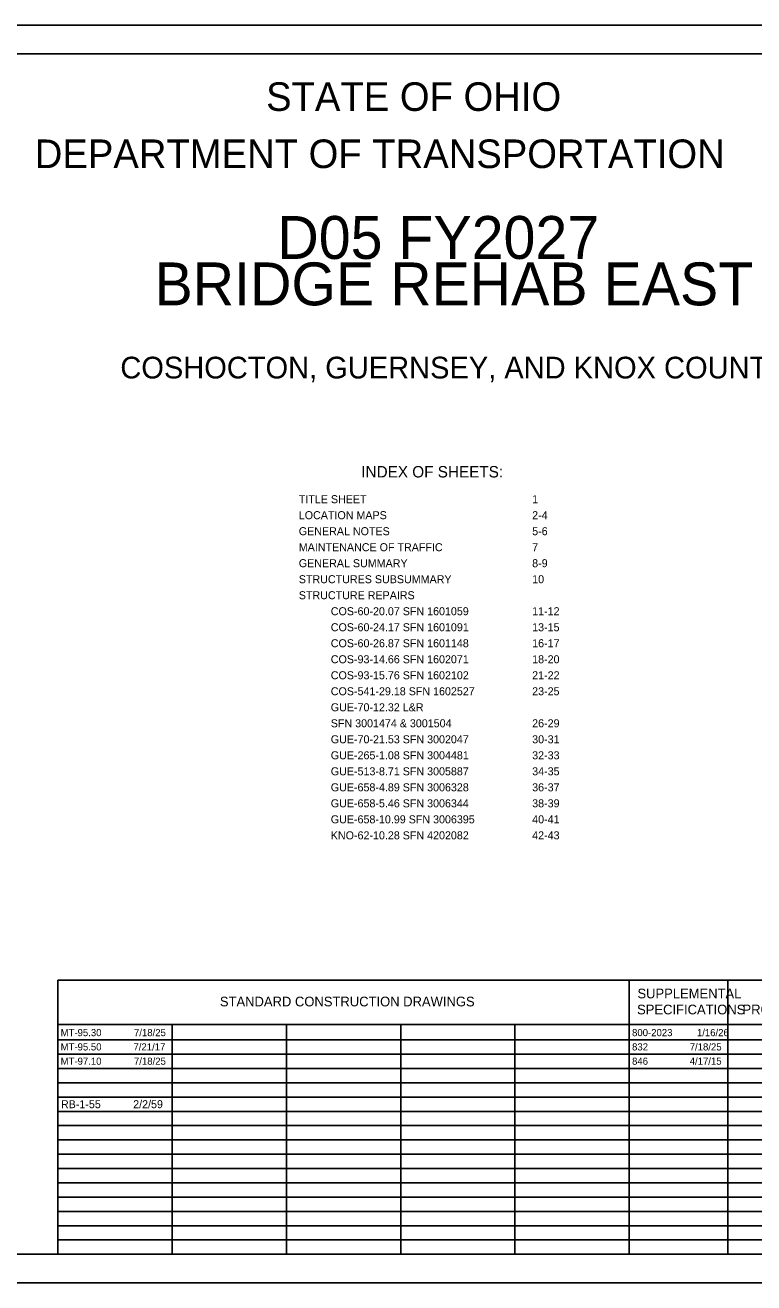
# Model space of a CAD drawing. Extents: x 0 to 34, y 0 to 22.
# Drawn here: x 9.58 to 22.33, y 0 to 22 of the extents above; entities that cross this region are included whole.
import ezdxf

# ---------------------------------------------------------------- set-up
doc = ezdxf.new("R2010")
doc.units = 0
for name, color, linetype in [('Default', 7, 'Continuous'), ('SH_Border', 7, 'Continuous'), ('SH_Cut_Line', 7, 'Continuous'), ('SH_Data', 7, 'Continuous'), ('SH_Text', 7, 'Continuous')]:
    doc.layers.add(name, color=color, linetype=linetype)

msp = doc.modelspace()

# ---------------------------------------------------------------- linework, layer by layer
at = {"layer": 'SH_Border'}
msp.add_lwpolyline([(1.5, 21.5), (33.5, 21.5), (33.5, 0.5), (1.5, 0.5)], close=True, dxfattribs=at)
at = {"layer": 'SH_Cut_Line'}
msp.add_lwpolyline([(0, 0), (34, 0), (34, 22), (0, 22)], close=True, dxfattribs=at)
at = {"layer": 'SH_Data'}
for p, q in [((10.15, 5.292), (23.6, 5.292)), ((10.15, 0.5), (10.15, 5.292)), ((20.15, 0.5), (20.15, 5.292)), ((21.875, 0.5), (21.875, 5.292)), ((10.15, 4.521), (23.6, 4.521)), ((12.15, 0.5), (12.15, 4.521)), ((14.15, 0.5), (14.15, 4.521)), ((16.15, 0.5), (16.15, 4.521)), ((18.15, 0.5), (18.15, 4.521)), ((10.15, 4.25), (23.6, 4.25)), ((10.15, 4), (23.6, 4)), ((10.15, 3.75), (23.6, 3.75)), ((10.15, 3.5), (23.6, 3.5)), ((10.15, 3.25), (23.6, 3.25)), ((10.15, 3), (23.6, 3)), ((10.15, 2.75), (23.6, 2.75)), ((10.15, 2.5), (23.6, 2.5)), ((10.15, 2.25), (23.6, 2.25)), ((10.15, 2), (23.6, 2)), ((10.15, 1.75), (23.6, 1.75)), ((10.15, 1.5), (23.6, 1.5)), ((10.15, 1.25), (23.6, 1.25)), ((10.15, 1), (23.6, 1)), ((10.15, 0.75), (23.6, 0.75))]:
    msp.add_line(p, q, dxfattribs=at)

# ---------------------------------------------------------------- texts
at = {"layer": 'Default'}
for s, p in [('MT-95.30', (10.199, 4.315)), ('7/18/25', (11.483, 4.315)), ('800-2023', (20.199, 4.315)), ('1/16/26', (21.334, 4.315)), ('MT-95.50', (10.199, 4.065)), ('7/21/17', (11.474, 4.065)), ('832', (20.199, 4.065)), ('7/18/25', (21.208, 4.065)), ('MT-97.10', (10.199, 3.815)), ('7/18/25', (11.483, 3.815)), ('846', (20.199, 3.815)), ('4/17/15', (21.208, 3.815))]:
    msp.add_text(s, height=0.125, dxfattribs=at).set_placement(p)
at = {"layer": 'SH_Text'}
for s, height, p in [('STATE OF OHIO', 0.5, (13.795, 20.5)), ('DEPARTMENT OF TRANSPORTATION', 0.5, (9.747, 19.5)), ('D05 FY2027', 0.75, (13.992, 17.911)), ('BRIDGE REHAB EAST', 0.75, (11.842, 17.099)), ('COSHOCTON, GUERNSEY, AND KNOX COUNTIES', 0.38, (11.244, 15.82)), ('INDEX OF SHEETS:', 0.2, (15.461, 14.088)), ('TITLE SHEET', 0.14, (14.367, 13.638)), ('1', 0.14, (18.451, 13.638)), ('LOCATION MAPS', 0.14, (14.367, 13.358)), ('2-4', 0.14, (18.451, 13.358)), ('GENERAL NOTES', 0.14, (14.367, 13.078)), ('5-6', 0.14, (18.451, 13.078)), ('MAINTENANCE OF TRAFFIC', 0.14, (14.367, 12.798)), ('7', 0.14, (18.451, 12.798)), ('GENERAL SUMMARY', 0.14, (14.367, 12.518)), ('8-9', 0.14, (18.451, 12.518)), ('STRUCTURES SUBSUMMARY', 0.14, (14.367, 12.238)), ('10', 0.14, (18.451, 12.238)), ('STRUCTURE REPAIRS', 0.14, (14.367, 11.958)), ('COS-60-20.07 SFN 1601059', 0.14, (14.927, 11.678)), ('11-12', 0.14, (18.451, 11.678)), ('COS-60-24.17 SFN 1601091', 0.14, (14.927, 11.398)), ('13-15', 0.14, (18.451, 11.398)), ('COS-60-26.87 SFN 1601148', 0.14, (14.927, 11.118)), ('16-17', 0.14, (18.451, 11.118)), ('COS-93-14.66 SFN 1602071', 0.14, (14.927, 10.838)), ('18-20', 0.14, (18.451, 10.838)), ('COS-93-15.76 SFN 1602102', 0.14, (14.927, 10.558)), ('21-22', 0.14, (18.451, 10.558)), ('COS-541-29.18 SFN 1602527', 0.14, (14.927, 10.278)), ('23-25', 0.14, (18.451, 10.278)), ('GUE-70-12.32 L&R ', 0.14, (14.927, 9.998)), ('SFN 3001474 & 3001504', 0.14, (14.927, 9.718)), ('26-29', 0.14, (18.451, 9.718)), ('GUE-70-21.53 SFN 3002047', 0.14, (14.927, 9.438)), ('30-31', 0.14, (18.451, 9.438)), ('GUE-265-1.08 SFN 3004481', 0.14, (14.927, 9.158)), ('32-33', 0.14, (18.451, 9.158)), ('GUE-513-8.71 SFN 3005887', 0.14, (14.927, 8.878)), ('34-35', 0.14, (18.451, 8.878)), ('GUE-658-4.89 SFN 3006328', 0.14, (14.927, 8.598)), ('36-37', 0.14, (18.451, 8.598)), ('GUE-658-5.46 SFN 3006344', 0.14, (14.927, 8.318)), ('38-39', 0.14, (18.451, 8.318)), ('GUE-658-10.99 SFN 3006395', 0.14, (14.927, 8.038)), ('40-41', 0.14, (18.451, 8.038)), ('KNO-62-10.28 SFN 4202082', 0.14, (14.927, 7.758)), ('42-43', 0.14, (18.451, 7.758)), ('SUPPLEMENTAL', 0.17, (20.293, 4.976)), ('STANDARD CONSTRUCTION DRAWINGS', 0.17, (12.986, 4.836)), ('SPECIFICATIONS', 0.17, (20.287, 4.696)), ('PROVISIONS', 0.17, (22.132, 4.696)), ('RB-1-55', 0.14, (10.205, 3.055)), ('2/2/59', 0.14, (11.469, 3.055))]:
    msp.add_text(s, height=height, dxfattribs=at).set_placement(p)

doc.saveas('drawing.dxf')
